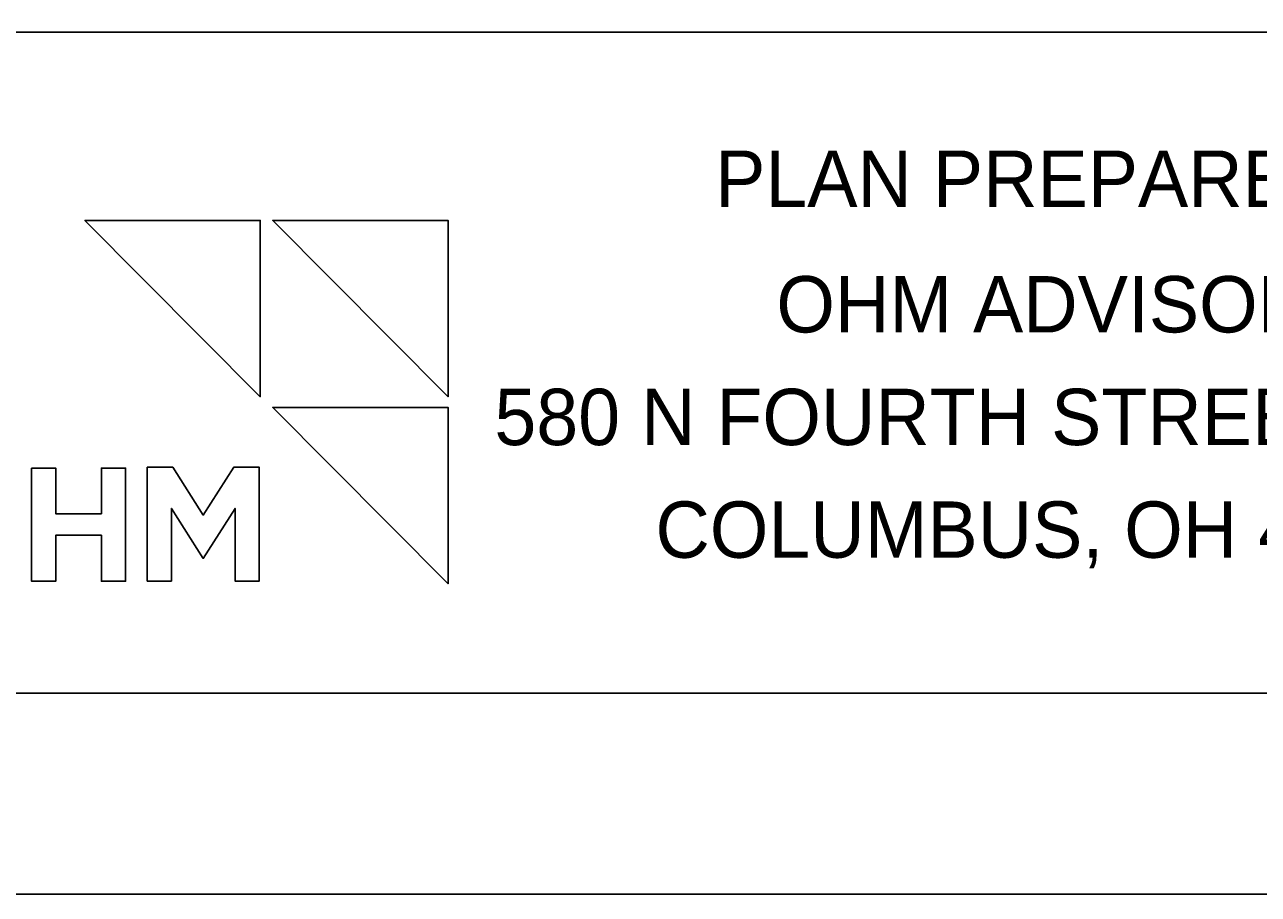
# Model space of a CAD drawing. Extents: x 0 to 34, y 0 to 22.
# Drawn here: x 2.67 to 5.736, y 0 to 2.161 of the extents above; entities that cross this region are included whole.
import ezdxf

# ---------------------------------------------------------------- set-up
doc = ezdxf.new("R2010")
doc.units = 0
for name, color, linetype in [('SH_Border', 7, 'Continuous'), ('SH_Cut_Line', 7, 'Continuous'), ('SH_Data', 7, 'Continuous'), ('SH_Named_Boundary', 7, 'Continuous'), ('SH_Text', 7, 'Continuous'), ('TX_P_Misc', 7, 'Continuous')]:
    doc.layers.add(name, color=color, linetype=linetype)

msp = doc.modelspace()

# ---------------------------------------------------------------- linework, layer by layer
at = {"layer": 'SH_Border'}
msp.add_lwpolyline([(1.5, 21.5), (33.5, 21.5), (33.5, 0.5), (1.5, 0.5)], close=True, dxfattribs=at)
at = {"layer": 'SH_Cut_Line'}
msp.add_lwpolyline([(0, 0), (34, 0), (34, 22), (0, 22)], close=True, dxfattribs=at)
at = {"layer": 'SH_Data'}
msp.add_line((6.6275, 2.1428), (2.3775, 2.1428), dxfattribs=at)
at = {"layer": 'SH_Named_Boundary'}
msp.add_lwpolyline([(2.3775, 2.1428), (6.6275, 2.1428), (6.6275, 0.5), (2.3775, 0.5)], close=True, dxfattribs=at)
at = {"layer": 'SH_Text'}
for points in [[(3.2558, 1.6748), (3.2558, 1.2366), (2.82, 1.6748)], [(3.7228, 1.6748), (3.7228, 1.2366), (3.287, 1.6748)], [(3.7228, 1.2099), (3.7228, 0.7717), (3.287, 1.2099)], [(2.6877, 1.0595), (2.7477, 1.0595), (2.7477, 0.946), (2.8612, 0.946), (2.8612, 1.0595), (2.9212, 1.0595), (2.9212, 0.7781), (2.8612, 0.7781), (2.8612, 0.8923), (2.7477, 0.8923), (2.7477, 0.7781), (2.6877, 0.7781)], [(3.1902, 1.0612), (3.2535, 1.0612), (3.2535, 0.7784), (3.1935, 0.7784), (3.1935, 0.9591), (3.1143, 0.8349), (3.0351, 0.9591), (3.0351, 0.7784), (2.9751, 0.7784), (2.9751, 1.0612), (3.0385, 1.0612), (3.1143, 0.9423)]]:
    msp.add_lwpolyline(points, close=True, dxfattribs=at)
at = {"layer": 'TX_P_Misc'}
for p, q in [((3.0351, 0.7784), (3.0351, 0.9591)), ((3.0351, 0.9591), (3.1143, 0.8349)), ((3.1143, 0.8349), (3.1935, 0.9591)), ((3.1935, 0.9591), (3.1935, 0.7784))]:
    msp.add_line(p, q, dxfattribs=at)
for points in [[(2.82, 1.6748), (3.2558, 1.2366), (3.2558, 1.6748), (2.82, 1.6748)], [(3.287, 1.6748), (3.7228, 1.2366), (3.7228, 1.6748), (3.287, 1.6748)], [(3.287, 1.2099), (3.7228, 0.7717), (3.7228, 1.2099), (3.287, 1.2099)], [(3.1143, 0.9423), (3.0385, 1.0612), (2.9751, 1.0612), (2.9751, 0.7784), (3.0351, 0.7784)], [(3.1935, 0.7784), (3.2535, 0.7784), (3.2535, 1.0612), (3.1902, 1.0612), (3.1143, 0.9423)]]:
    msp.add_lwpolyline(points, dxfattribs=at)
msp.add_lwpolyline([(2.6877, 1.0595), (2.7477, 1.0595), (2.7477, 0.946), (2.8612, 0.946), (2.8612, 1.0595), (2.9212, 1.0595), (2.9212, 0.7781), (2.8612, 0.7781), (2.8612, 0.8923), (2.7477, 0.8923), (2.7477, 0.7781), (2.6877, 0.7781)], close=True, dxfattribs=at)

# ---------------------------------------------------------------- texts
at = {"layer": 'SH_Text'}
for s, p in [('PLAN PREPARED BY:', (4.3864, 1.7084)), ('OHM ADVISORS', (4.5385, 1.3964)), ('580 N FOURTH STREET, STE 610', (3.8378, 1.1164)), ('COLUMBUS, OH 43215', (4.238, 0.8364))]:
    msp.add_text(s, height=0.14, dxfattribs=at).set_placement(p)

doc.saveas('drawing.dxf')
